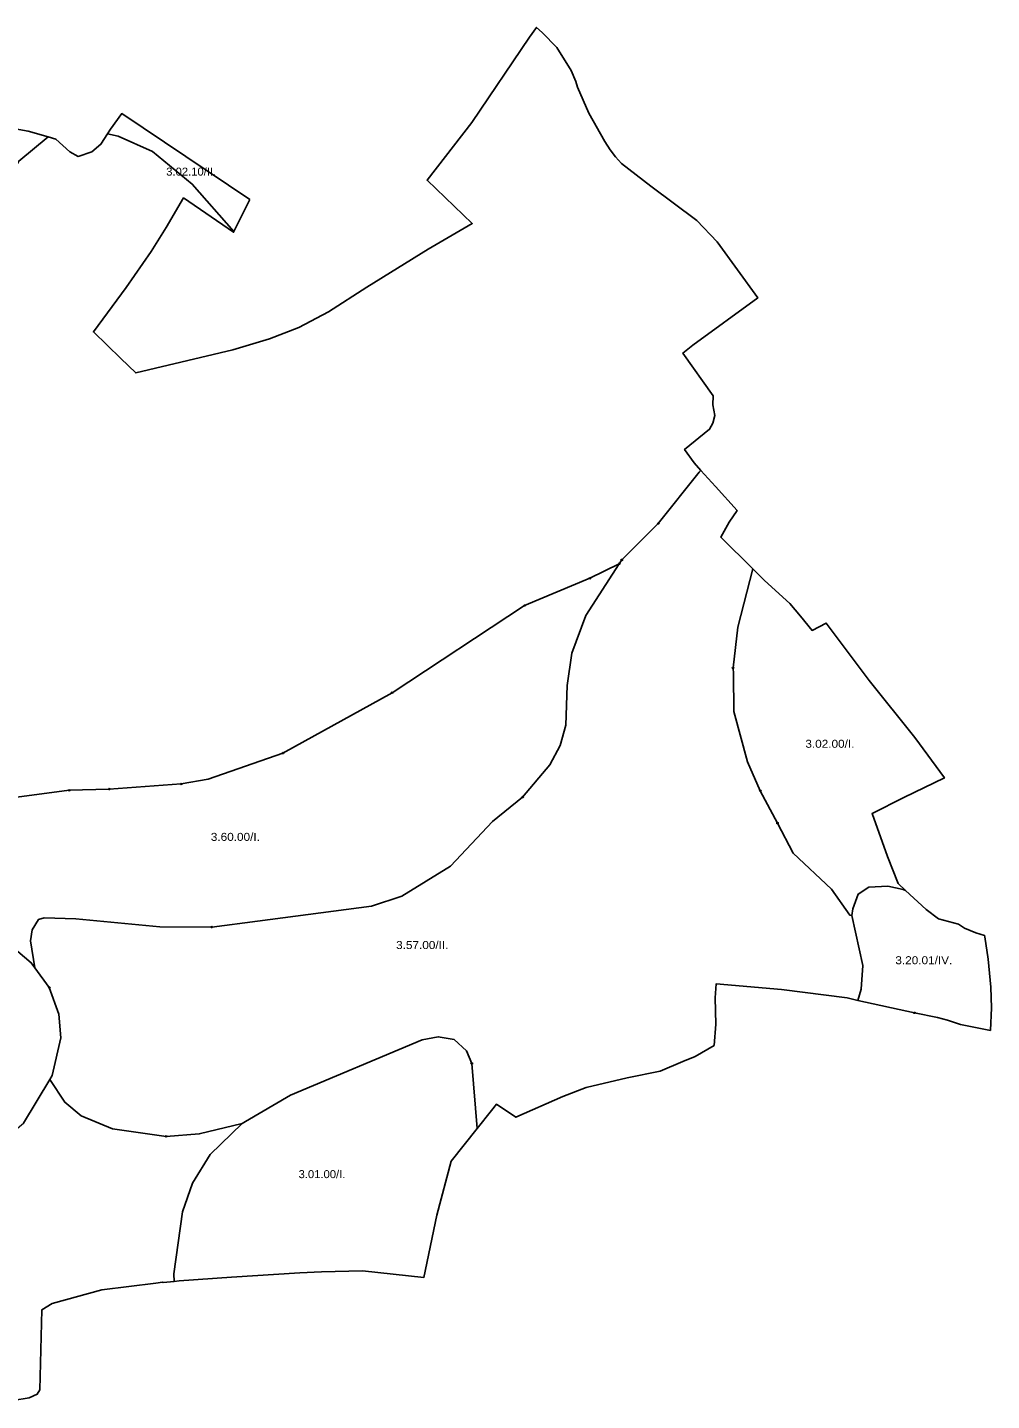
# Model space of a CAD drawing. Extents: x -650455 to -642254, y -1075222 to -1066610.
# Drawn here: x -643459 to -642254, y -1070722 to -1069006 of the extents above; entities that cross this region are included whole.
import ezdxf
from ezdxf.enums import TextEntityAlignment as Align

# ---------------------------------------------------------------- set-up
doc = ezdxf.new("R2010")
doc.units = 0
doc.header["$LTSCALE"] = 4
doc.header["$PDMODE"] = 32
doc.header["$PDSIZE"] = 2
for name, color, linetype, lineweight in [('1', 7, 'Continuous', 25), ('11', 7, 'Continuous', 13), ('12', 7, 'Continuous', 13), ('14', 7, 'Continuous', 13)]:
    doc.layers.add(name, color=color, linetype=linetype, lineweight=lineweight)
doc.layers.add('2', color=7, linetype='Continuous')

msp = doc.modelspace()

# ---------------------------------------------------------------- linework, layer by layer
at = {"layer": '1'}
for points in [[(-643253, -1069201.5), (-643200.685, -1069260.355), (-643201.204, -1069261.41), (-643263.608, -1069218.549), (-643285.341, -1069255.509), (-643304.279, -1069285.638), (-643335.326, -1069330.673), (-643376.308, -1069385.959), (-643342.157, -1069419.193), (-643323.529, -1069437.207), (-643202.136, -1069408.632), (-643156.187, -1069394.655), (-643119.552, -1069380.678), (-643082.606, -1069360.801), (-643034.794, -1069330.052), (-642958.109, -1069282.531), (-642902.846, -1069250.54), (-642959.282, -1069196.43), (-642903.444, -1069124.462), (-642831.547, -1069017.823), (-642822.603, -1069005.526), (-642815.422, -1069011.749), (-642797.105, -1069030.384), (-642779.422, -1069059.24), (-642773.657, -1069073.076), (-642771.588, -1069080.346), (-642757.371, -1069112.568), (-642737.193, -1069148.167), (-642730.707, -1069158.4), (-642723.789, -1069167.336), (-642716.252, -1069175.573), (-642679.927, -1069203.837), (-642622.18, -1069247.009), (-642596.722, -1069273.41), (-642546.116, -1069343.605), (-642627.309, -1069402.672), (-642639.728, -1069412.612), (-642601.851, -1069466.034), (-642602.161, -1069477.215), (-642599.988, -1069490.572)], [(-643469.5, -1069172.501), (-643432.983, -1069142.138), (-643423.189, -1069144.938), (-643405.803, -1069161.088), (-643395.557, -1069166.679), (-643378.481, -1069160.778), (-643366.994, -1069151.459), (-643358.703, -1069138.487), (-643345.5, -1069141.5), (-643302.5, -1069160.501), (-643253, -1069201.5)], [(-642599.988, -1069490.572), (-642602.471, -1069500.2), (-642606.508, -1069507.654), (-642637.554, -1069533.122), (-642625.757, -1069549.894), (-642617.261, -1069559.279)], [(-642617.261, -1069559.279), (-642619.5, -1069561.501), (-642670.5, -1069625.501), (-642716, -1069671), (-642719.154, -1069675.872), (-642756, -1069694.001), (-642837.5, -1069728), (-643003, -1069837), (-643139.5, -1069912.501), (-643233, -1069945.001), (-643266.5, -1069951), (-643356.5, -1069957.501), (-643406.5, -1069959), (-643472, -1069967.5)], [(-643244, -1070388.5), (-643285.5, -1070391.501), (-643352.5, -1070382.001), (-643391.5, -1070366.001), (-643412, -1070349), (-643431, -1070320.5), (-643428, -1070315.5), (-643417, -1070268.501), (-643419.5, -1070239), (-643431.5, -1070205.5), (-643449.5, -1070181.001), (-643455, -1070147.001), (-643453, -1070133.5), (-643445, -1070120.5), (-643438, -1070118.501), (-643398.5, -1070119.501), (-643293.5, -1070129.5), (-643228.5, -1070130), (-643171.5, -1070122.501), (-643029, -1070104.001), (-642991, -1070091.501), (-642930, -1070054.001), (-642877.5, -1069998.001), (-642840, -1069967.5), (-642806, -1069927), (-642793, -1069903), (-642786, -1069877.5), (-642784.5, -1069828.001), (-642778.5, -1069787.501), (-642761, -1069740.5), (-642719.154, -1069675.872), (-642716, -1069671), (-642670.5, -1069625.501), (-642619.5, -1069561.501), (-642617.261, -1069559.279), (-642599.044, -1069579.399), (-642572.046, -1069609.218), (-642581.981, -1069623.817), (-642592.226, -1069642.762), (-642552.355, -1069682.197)], [(-643472, -1069967.5), (-643406.5, -1069959), (-643356.5, -1069957.501), (-643266.5, -1069951), (-643233, -1069945.001), (-643139.5, -1069912.501), (-643003, -1069837), (-642837.5, -1069728), (-642756, -1069694.001), (-642719.154, -1069675.872), (-642761, -1069740.5), (-642778.5, -1069787.501), (-642784.5, -1069828.001), (-642786, -1069877.5), (-642793, -1069903), (-642806, -1069927), (-642840, -1069967.5), (-642877.5, -1069998.001), (-642930, -1070054.001), (-642991, -1070091.501), (-643029, -1070104.001), (-643171.5, -1070122.501)], [(-642552.355, -1069682.197), (-642571, -1069755.001), (-642577, -1069806), (-642576.5, -1069813.5), (-642576, -1069860.501), (-642559, -1069923.5), (-642543, -1069959.5), (-642521.5, -1070000), (-642502, -1070037.501), (-642454, -1070082.501), (-642431, -1070115.001), (-642428.5, -1070115.501), (-642415, -1070178), (-642417, -1070207.501), (-642420.956, -1070221.525), (-642434.435, -1070218.539), (-642516.398, -1070207.98), (-642598.051, -1070200.836), (-642599.293, -1070218.539), (-642598.672, -1070251.463), (-642600.535, -1070277.863), (-642624.441, -1070291.84), (-642639.802, -1070298.162), (-642668.217, -1070309.854), (-642709.509, -1070318.552), (-642760.737, -1070330.354), (-642789.61, -1070341.846), (-642848.288, -1070367.626), (-642872.815, -1070351.474), (-642878.961, -1070359.21), (-642896.975, -1070381.886), (-642903.5, -1070300.5), (-642910, -1070284.501), (-642925.5, -1070270.5), (-642945.5, -1070267), (-642965.5, -1070271), (-643130, -1070340), (-643186.433, -1070373.114), (-643190.5, -1070375.5), (-643244, -1070388.5)], [(-643171.5, -1070122.501), (-643228.5, -1070130), (-643293.5, -1070129.5), (-643398.5, -1070119.501), (-643438, -1070118.501), (-643445, -1070120.5), (-643453, -1070133.5), (-643455, -1070147.001), (-643449.5, -1070181.001)], [(-643479, -1070153.5), (-643454, -1070174.5), (-643449.5, -1070181.001), (-643431.5, -1070205.5), (-643419.5, -1070239), (-643417, -1070268.501), (-643428, -1070315.5), (-643431, -1070320.5), (-643463.5, -1070375.001)], [(-643449.5, -1070181.001), (-643454, -1070174.5), (-643479, -1070153.5)], [(-643463.5, -1070375.001), (-643431, -1070320.5), (-643412, -1070349), (-643391.5, -1070366.001), (-643352.5, -1070382.001), (-643285.5, -1070391.501), (-643244, -1070388.5), (-643190.5, -1070375.5), (-643230.5, -1070414.001), (-643252.5, -1070450), (-643265, -1070486), (-643276, -1070563.5), (-643275.344, -1070572.875), (-643289.061, -1070574.177), (-643290.031, -1070573.836), (-643298.218, -1070574.877), (-643365.785, -1070583.463), (-643427.878, -1070600.237), (-643440.607, -1070608.311), (-643443.091, -1070708.324), (-643446.816, -1070713.915), (-643456.751, -1070718.263), (-643476.945, -1070721.725)]]:
    msp.add_lwpolyline(points, dxfattribs=at)
for points in [[(-643181.023, -1069220.412), (-643200.685, -1069260.355), (-643253, -1069201.5), (-643302.5, -1069160.501), (-643345.5, -1069141.5), (-643358.703, -1069138.487), (-643354.885, -1069132.514), (-643340.914, -1069113.257)], [(-643513, -1069247), (-643526, -1069259), (-643519, -1069241.501), (-643517, -1069208.001), (-643523, -1069163.001), (-643536.575, -1069133.589), (-643483.419, -1069130.65), (-643457.961, -1069134.998), (-643432.983, -1069142.138), (-643469.5, -1069172.501)], [(-642361.321, -1070084.08), (-642364.5, -1070083.001), (-642383.5, -1070079.001), (-642407.5, -1070080), (-642420.5, -1070089), (-642427.5, -1070107.001), (-642428.5, -1070115.501), (-642431, -1070115.001), (-642454, -1070082.501), (-642502, -1070037.501), (-642521.5, -1070000), (-642543, -1069959.5), (-642559, -1069923.5), (-642576, -1069860.501), (-642576.5, -1069813.5), (-642577, -1069806), (-642571, -1069755.001), (-642552.355, -1069682.197), (-642537.584, -1069696.806), (-642505.916, -1069725.382), (-642492.836, -1069741.408), (-642478.285, -1069759.236), (-642460.588, -1069750.229), (-642406.877, -1069821.665), (-642349.751, -1069892.791), (-642312.805, -1069943.419), (-642363.412, -1069967.956), (-642403.152, -1069987.834), (-642383.903, -1070041.878), (-642370.553, -1070075.422)], [(-642361.321, -1070084.08), (-642335.781, -1070108.035), (-642320.258, -1070119.527), (-642295.202, -1070126.517), (-642287.754, -1070131.386), (-642273.43, -1070137.117), (-642262.687, -1070140.46), (-642262.467, -1070141.96), (-642258.374, -1070169.876), (-642254.86, -1070204.888), (-642254.016, -1070230.758), (-642255.33, -1070259.177), (-642292.811, -1070251.773), (-642309.077, -1070246.214), (-642321.735, -1070243.076), (-642350.298, -1070237.176), (-642420.956, -1070221.525), (-642417, -1070207.501), (-642415, -1070178), (-642428.5, -1070115.501), (-642427.5, -1070107.001), (-642420.5, -1070089), (-642407.5, -1070080), (-642383.5, -1070079.001), (-642364.5, -1070083.001)], [(-642896.975, -1070381.886), (-642929.32, -1070422.6), (-642947.327, -1070490), (-642963.471, -1070567.958), (-643040.151, -1070559.763), (-643091.317, -1070560.773), (-643118.269, -1070562.07), (-643203.593, -1070567.547), (-643269.316, -1070572.302), (-643275.344, -1070572.875), (-643276, -1070563.5), (-643265, -1070486), (-643252.5, -1070450), (-643230.5, -1070414.001), (-643190.5, -1070375.5), (-643186.433, -1070373.114), (-643130, -1070340), (-642965.5, -1070271), (-642945.5, -1070267), (-642925.5, -1070270.5), (-642910, -1070284.501), (-642903.5, -1070300.5)]]:
    msp.add_lwpolyline(points, close=True, dxfattribs=at)
at = {"layer": '11'}
for p, q in [((-642756, -1069694.001), (-642719.154, -1069675.872)), ((-643139.5, -1069912.501), (-643003, -1069837)), ((-643406.5, -1069959), (-643356.5, -1069957.501)), ((-642543, -1069959.5), (-642521.5, -1070000))]:
    msp.add_line(p, q, dxfattribs=at)
for points in [[(-642670.5, -1069625.501), (-642619.5, -1069561.501), (-642617.261, -1069559.279), (-642625.757, -1069549.894), (-642637.554, -1069533.122), (-642606.508, -1069507.654), (-642602.471, -1069500.2), (-642599.988, -1069490.572), (-642602.161, -1069477.215), (-642601.851, -1069466.034), (-642639.728, -1069412.612), (-642627.309, -1069402.672), (-642546.116, -1069343.605), (-642596.722, -1069273.41), (-642622.18, -1069247.009), (-642679.927, -1069203.837), (-642716.252, -1069175.573), (-642723.789, -1069167.336), (-642730.707, -1069158.4), (-642737.193, -1069148.167), (-642757.371, -1069112.568), (-642771.588, -1069080.346), (-642773.657, -1069073.076), (-642779.422, -1069059.24), (-642797.105, -1069030.384), (-642815.422, -1069011.749), (-642822.603, -1069005.526), (-642831.547, -1069017.823), (-642903.444, -1069124.462), (-642959.282, -1069196.43), (-642902.846, -1069250.54), (-642958.109, -1069282.531), (-643034.794, -1069330.052), (-643082.606, -1069360.801), (-643119.552, -1069380.678), (-643156.187, -1069394.655), (-643202.136, -1069408.632), (-643323.529, -1069437.207), (-643342.157, -1069419.193), (-643376.308, -1069385.959)], [(-643376.308, -1069385.959), (-643335.326, -1069330.673), (-643304.279, -1069285.638), (-643285.341, -1069255.509), (-643263.608, -1069218.549), (-643201.204, -1069261.41), (-643200.685, -1069260.355), (-643253, -1069201.5), (-643302.5, -1069160.501), (-643345.5, -1069141.5), (-643358.703, -1069138.487), (-643366.994, -1069151.459), (-643378.481, -1069160.778), (-643395.557, -1069166.679), (-643405.803, -1069161.088), (-643423.189, -1069144.938), (-643432.983, -1069142.138), (-643469.5, -1069172.501)], [(-642719.154, -1069675.872), (-642716, -1069671), (-642670.5, -1069625.501)], [(-642840, -1069967.5), (-642806, -1069927), (-642793, -1069903), (-642786, -1069877.5), (-642784.5, -1069828.001), (-642778.5, -1069787.501), (-642761, -1069740.5), (-642719.154, -1069675.872), (-642756, -1069694.001), (-642837.5, -1069728)], [(-642521.5, -1070000), (-642502, -1070037.501), (-642454, -1070082.501), (-642431, -1070115.001), (-642428.5, -1070115.501), (-642427.5, -1070107.001), (-642420.5, -1070089), (-642407.5, -1070080), (-642383.5, -1070079.001), (-642364.5, -1070083.001), (-642361.321, -1070084.08), (-642370.553, -1070075.422), (-642383.903, -1070041.878), (-642403.152, -1069987.834), (-642363.412, -1069967.956), (-642312.805, -1069943.419), (-642349.751, -1069892.791), (-642406.877, -1069821.665), (-642460.588, -1069750.229), (-642478.285, -1069759.236), (-642492.836, -1069741.408), (-642505.916, -1069725.382), (-642537.584, -1069696.806), (-642552.355, -1069682.197), (-642571, -1069755.001), (-642577, -1069806), (-642576.5, -1069813.5), (-642576, -1069860.501)], [(-643003, -1069837), (-642837.5, -1069728), (-642756, -1069694.001)], [(-642837.5, -1069728), (-643003, -1069837), (-643139.5, -1069912.501), (-643233, -1069945.001), (-643266.5, -1069951)], [(-642576, -1069860.501), (-642559, -1069923.5), (-642543, -1069959.5)], [(-643356.5, -1069957.501), (-643266.5, -1069951), (-643233, -1069945.001), (-643139.5, -1069912.501)], [(-643266.5, -1069951), (-643356.5, -1069957.501), (-643406.5, -1069959), (-643472, -1069967.5), (-643488, -1069984), (-643502, -1070023.001)], [(-643488, -1069984), (-643472, -1069967.5), (-643406.5, -1069959)], [(-643228.5, -1070130), (-643171.5, -1070122.501), (-643029, -1070104.001), (-642991, -1070091.501), (-642930, -1070054.001), (-642877.5, -1069998.001), (-642840, -1069967.5)], [(-643479, -1070153.5), (-643454, -1070174.5), (-643449.5, -1070181.001), (-643455, -1070147.001), (-643453, -1070133.5), (-643445, -1070120.5), (-643438, -1070118.501), (-643398.5, -1070119.501), (-643293.5, -1070129.5), (-643228.5, -1070130)], [(-643622, -1070455.001), (-643537.5, -1070424.5), (-643490, -1070397), (-643463.5, -1070375.001), (-643431, -1070320.5), (-643428, -1070315.5), (-643417, -1070268.501), (-643419.5, -1070239), (-643431.5, -1070205.5), (-643449.5, -1070181.001), (-643454, -1070174.5), (-643479, -1070153.5), (-643508.5, -1070145.5)], [(-642903.5, -1070300.5), (-642910, -1070284.501), (-642925.5, -1070270.5), (-642945.5, -1070267), (-642965.5, -1070271), (-643130, -1070340), (-643186.433, -1070373.114), (-643190.5, -1070375.5), (-643230.5, -1070414.001), (-643252.5, -1070450), (-643265, -1070486), (-643276, -1070563.5)], [(-643276, -1070563.5), (-643275.344, -1070572.875), (-643269.316, -1070572.302), (-643203.593, -1070567.547), (-643118.269, -1070562.07), (-643091.317, -1070560.773), (-643040.151, -1070559.763), (-642963.471, -1070567.958), (-642947.327, -1070490), (-642929.32, -1070422.6), (-642896.975, -1070381.886), (-642903.5, -1070300.5)], [(-643476.945, -1070721.725), (-643456.751, -1070718.263), (-643446.816, -1070713.915), (-643443.091, -1070708.324), (-643440.607, -1070608.311), (-643427.878, -1070600.237), (-643365.785, -1070583.463), (-643298.218, -1070574.877), (-643290.031, -1070573.836), (-643289.061, -1070574.177), (-643275.344, -1070572.875), (-643276, -1070563.5), (-643265, -1070486), (-643252.5, -1070450), (-643230.5, -1070414.001), (-643190.5, -1070375.5), (-643244, -1070388.5), (-643285.5, -1070391.501), (-643352.5, -1070382.001), (-643391.5, -1070366.001), (-643412, -1070349), (-643431, -1070320.5), (-643463.5, -1070375.001)]]:
    msp.add_lwpolyline(points, dxfattribs=at)
for p in [(-642670.5, -1069625.501), (-642719.154, -1069675.872), (-642756, -1069694.001), (-642837.5, -1069728), (-643003, -1069837), (-643139.5, -1069912.501), (-643406.5, -1069959), (-643356.5, -1069957.501), (-643266.5, -1069951), (-642543, -1069959.5), (-642840, -1069967.5), (-642521.5, -1070000), (-643228.5, -1070130), (-642903.5, -1070300.5)]:
    msp.add_point(p, dxfattribs=at)
at = {"layer": '12'}
for points in [[(-643200.685, -1069260.355), (-643181.023, -1069220.412), (-643340.914, -1069113.257), (-643354.885, -1069132.514), (-643358.703, -1069138.487), (-643345.5, -1069141.5), (-643302.5, -1069160.501), (-643253, -1069201.5)], [(-643519, -1069241.501), (-643526, -1069259), (-643513, -1069247), (-643469.5, -1069172.501), (-643432.983, -1069142.138), (-643457.961, -1069134.998), (-643483.419, -1069130.65), (-643536.575, -1069133.589), (-643523, -1069163.001), (-643517, -1069208.001)]]:
    msp.add_lwpolyline(points, close=True, dxfattribs=at)
for points in [[(-642577, -1069806), (-642571, -1069755.001), (-642552.355, -1069682.197), (-642592.226, -1069642.762), (-642581.981, -1069623.817), (-642572.046, -1069609.218), (-642599.044, -1069579.399), (-642617.261, -1069559.279), (-642619.5, -1069561.501), (-642670.5, -1069625.501), (-642716, -1069671)], [(-642716, -1069671), (-642719.154, -1069675.872), (-642761, -1069740.5), (-642778.5, -1069787.501), (-642784.5, -1069828.001), (-642786, -1069877.5), (-642793, -1069903), (-642806, -1069927), (-642840, -1069967.5), (-642877.5, -1069998.001), (-642930, -1070054.001), (-642991, -1070091.501), (-643029, -1070104.001), (-643171.5, -1070122.501), (-643228.5, -1070130), (-643293.5, -1070129.5), (-643398.5, -1070119.501), (-643438, -1070118.501), (-643445, -1070120.5), (-643453, -1070133.5), (-643455, -1070147.001), (-643449.5, -1070181.001), (-643431.5, -1070205.5)], [(-643285.5, -1070391.501), (-643244, -1070388.5), (-643190.5, -1070375.5), (-643186.433, -1070373.114), (-643130, -1070340), (-642965.5, -1070271), (-642945.5, -1070267), (-642925.5, -1070270.5), (-642910, -1070284.501), (-642903.5, -1070300.5), (-642896.975, -1070381.886), (-642878.961, -1070359.21), (-642872.815, -1070351.474), (-642848.288, -1070367.626), (-642789.61, -1070341.846), (-642760.737, -1070330.354), (-642709.509, -1070318.552), (-642668.217, -1070309.854), (-642639.802, -1070298.162), (-642624.441, -1070291.84), (-642600.535, -1070277.863), (-642598.672, -1070251.463), (-642599.293, -1070218.539), (-642598.051, -1070200.836), (-642516.398, -1070207.98), (-642434.435, -1070218.539), (-642420.956, -1070221.525), (-642417, -1070207.501), (-642415, -1070178), (-642428.5, -1070115.501), (-642431, -1070115.001), (-642454, -1070082.501), (-642502, -1070037.501), (-642521.5, -1070000), (-642543, -1069959.5), (-642559, -1069923.5), (-642576, -1069860.501), (-642576.5, -1069813.5), (-642577, -1069806)], [(-643431.5, -1070205.5), (-643419.5, -1070239), (-643417, -1070268.501), (-643428, -1070315.5), (-643431, -1070320.5), (-643412, -1070349), (-643391.5, -1070366.001), (-643352.5, -1070382.001), (-643285.5, -1070391.501)]]:
    msp.add_lwpolyline(points, dxfattribs=at)
for p in [(-642716, -1069671), (-642577, -1069806), (-643431.5, -1070205.5), (-643285.5, -1070391.501)]:
    msp.add_point(p, dxfattribs=at)
at = {"layer": '14'}
msp.add_lwpolyline([(-642350.298, -1070237.176), (-642321.735, -1070243.076), (-642309.077, -1070246.214), (-642292.811, -1070251.773), (-642255.33, -1070259.177), (-642254.016, -1070230.758), (-642254.86, -1070204.888), (-642258.374, -1070169.876), (-642262.467, -1070141.96), (-642262.687, -1070140.46), (-642273.43, -1070137.117), (-642287.754, -1070131.386), (-642295.202, -1070126.517), (-642320.258, -1070119.527), (-642335.781, -1070108.035), (-642361.321, -1070084.08), (-642364.5, -1070083.001), (-642383.5, -1070079.001), (-642407.5, -1070080), (-642420.5, -1070089), (-642427.5, -1070107.001), (-642428.5, -1070115.501), (-642415, -1070178), (-642417, -1070207.501), (-642420.956, -1070221.525)], close=True, dxfattribs=at)
msp.add_point((-642350.298, -1070237.176), dxfattribs=at)

# ---------------------------------------------------------------- texts
at = {"layer": '2'}
for s, width, p in [('3.02.10/II.', 1.05, (-643254.154, -1069190.685)), ('3.02.00/I.', 1.1, (-642456.002, -1069905.833)), ('3.60.00/I.', 1.1, (-643198.943, -1070022.212)), ('3.57.00/II.', 1.1, (-642965.377, -1070157.389)), ('3.20.01/IV.', 1.1, (-642338.615, -1070176.387)), ('3.01.00/I.', 1.05, (-643090.713, -1070443.748))]:
    msp.add_text(s, height=10, dxfattribs=dict(at, width=width)).set_placement(p, align=Align.CENTER)

doc.saveas('drawing.dxf')
